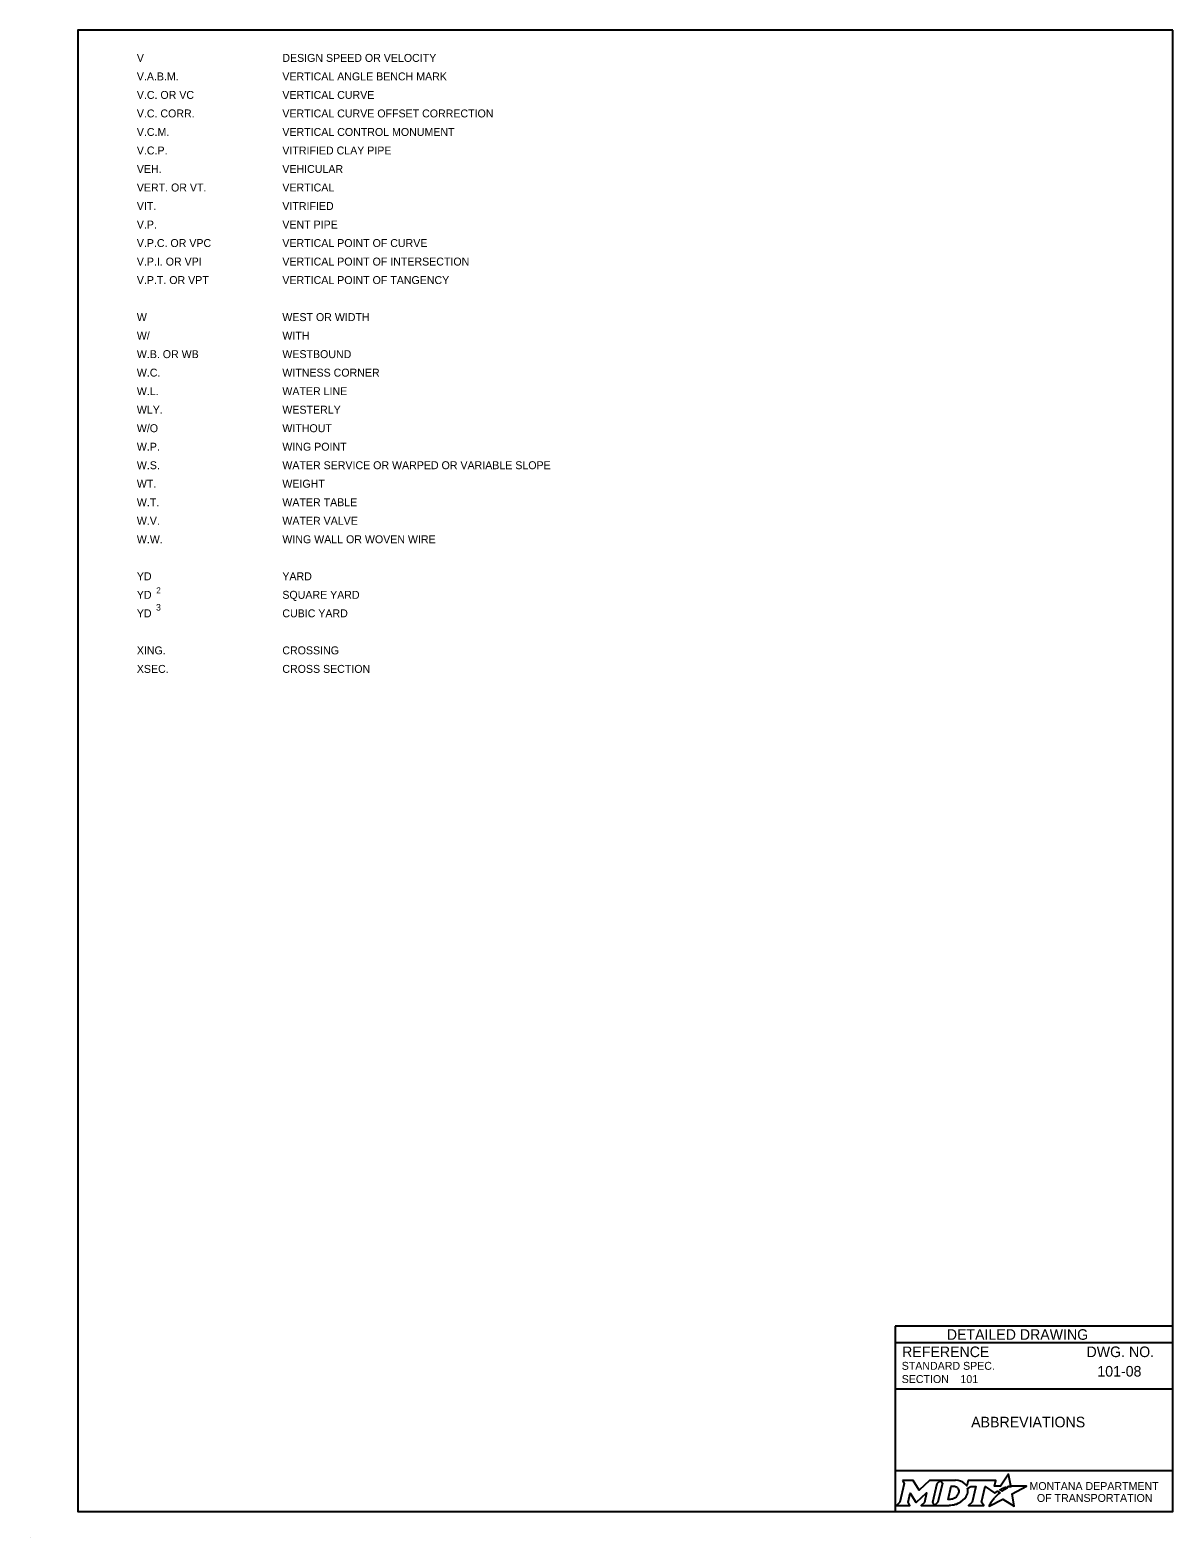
# Model space of a CAD drawing. Extents: x 49991.4 to 50021, y 49987.6 to 50011.4.
# Drawn here: x 49999.98 to 50008.61, y 49999.86 to 50011.26 of the extents above; entities that cross this region are included whole.
import ezdxf

# ---------------------------------------------------------------- set-up
doc = ezdxf.new("R2010")
doc.units = 0
for name, color, linetype in [('Default', 7, 'Continuous'), ('Level 1', 7, 'Continuous'), ('Level 2', 7, 'Continuous'), ('Level 5', 7, 'Continuous')]:
    doc.layers.add(name, color=color, linetype=linetype)

msp = doc.modelspace()

# ---------------------------------------------------------------- linework, layer by layer
at = {"layer": 'Level 1'}
msp.add_line((49999.977, 49999.862), (49999.977, 49999.862), dxfattribs=at)
msp.add_lwpolyline([(50008.615, 50011.263), (50000.336, 50011.263), (50000.336, 50000.062), (50008.615, 50000.062)], close=True, dxfattribs=at)
at = {"layer": 'Level 2'}
for p, q in [((50008.615, 50001.462), (50006.515, 50001.462)), ((50006.515, 50001.462), (50006.515, 50000.062)), ((50008.615, 50001.337), (50006.515, 50001.337)), ((50007.009, 50001.063), (50007.009, 50001.063)), ((50008.251, 50001.122), (50008.251, 50001.122)), ((50008.615, 50000.987), (50006.515, 50000.987)), ((50007.565, 50000.738), (50007.565, 50000.738)), ((50008.615, 50000.369), (50006.515, 50000.369))]:
    msp.add_line(p, q, dxfattribs=at)
for points in [[(50007.377, 50000.245), (50007.367, 50000.25), (50007.378, 50000.253), (50007.39, 50000.255), (50007.373, 50000.345), (50007.313, 50000.254), (50007.266, 50000.253), (50007.276, 50000.297), (50007.067, 50000.297), (50007.057, 50000.255), (50007.051, 50000.263)], [(50006.57, 50000.297), (50006.584, 50000.274), (50006.551, 50000.131), (50006.525, 50000.108), (50006.627, 50000.108), (50006.613, 50000.131), (50006.629, 50000.201), (50006.673, 50000.132), (50006.678, 50000.132), (50006.753, 50000.202), (50006.737, 50000.13), (50006.712, 50000.108), (50006.814, 50000.108), (50006.8, 50000.132), (50006.833, 50000.274)], [(50006.833, 50000.274), (50006.859, 50000.297), (50006.776, 50000.297), (50006.697, 50000.224), (50006.652, 50000.297), (50006.57, 50000.297)], [(50006.972, 50000.297), (50006.859, 50000.297), (50006.873, 50000.275), (50006.839, 50000.131), (50006.814, 50000.108), (50006.925, 50000.108)], [(50006.996, 50000.211), (50006.995, 50000.203), (50006.992, 50000.193), (50006.988, 50000.185), (50006.982, 50000.178), (50006.976, 50000.171), (50006.968, 50000.164), (50006.959, 50000.16), (50006.95, 50000.156), (50006.941, 50000.154), (50006.932, 50000.153), (50006.916, 50000.153), (50006.94, 50000.253), (50006.956, 50000.253), (50006.963, 50000.252), (50006.971, 50000.25), (50006.977, 50000.247), (50006.983, 50000.243), (50006.988, 50000.238), (50006.992, 50000.232), (50006.995, 50000.226), (50006.996, 50000.218), (50006.996, 50000.215), (50006.996, 50000.211)], [(50007.064, 50000.238), (50007.088, 50000.251), (50007.125, 50000.251), (50007.097, 50000.131), (50007.069, 50000.108), (50007.185, 50000.108), (50007.168, 50000.131), (50007.196, 50000.251), (50007.268, 50000.2), (50007.289, 50000.215), (50007.309, 50000.204)], [(50007.253, 50000.148), (50007.237, 50000.124), (50007.233, 50000.116), (50007.227, 50000.107), (50007.225, 50000.103), (50007.33, 50000.156), (50007.414, 50000.101), (50007.401, 50000.194), (50007.508, 50000.252), (50007.458, 50000.253), (50007.428, 50000.253), (50007.407, 50000.254), (50007.401, 50000.252), (50007.396, 50000.251), (50007.387, 50000.249), (50007.377, 50000.245)], [(50007.327, 50000.217), (50007.324, 50000.215), (50007.306, 50000.225), (50007.316, 50000.231), (50007.32, 50000.233), (50007.329, 50000.237), (50007.335, 50000.239), (50007.343, 50000.243), (50007.35, 50000.245), (50007.362, 50000.238), (50007.358, 50000.236), (50007.353, 50000.233), (50007.349, 50000.231), (50007.344, 50000.228), (50007.342, 50000.227), (50007.339, 50000.225), (50007.337, 50000.224), (50007.334, 50000.222), (50007.332, 50000.221), (50007.329, 50000.219), (50007.327, 50000.217)], [(50006.97, 50000.116), (50006.979, 50000.118), (50006.992, 50000.124), (50007.012, 50000.135)], [(50007.267, 50000.164), (50007.267, 50000.164)]]:
    msp.add_lwpolyline(points, dxfattribs=at)
for centre, radius, start, end in [((50006.995, 50000.219), 0.0709, 339.5329, 15.8582), ((50006.951, 50000.236), 0.118, 300.9103, 339.1383)]:
    msp.add_arc(centre, radius, start, end, dxfattribs=at)
for centre, major_axis, ratio, start_param, end_param in [((50006.97, 50000.25), (0.0834, -0.0037), 0.568097, 0.61298, 1.570796), ((50007.026, 50000.257), (0.0361, -0.0295), 0.469099, 1.225588, 1.570796), ((50006.925, 50000.257), (0, 0.148), 0.987302, 3.139398, 3.456847), ((50007.26, 50000.156), (-0.00694, -0.00806), 0.008222, 0, 3.137361), ((50007.276, 50000.174), (-0.0098, -0.0102), 0.016458, 3.141593, 6.279097), ((50007.297, 50000.194), (-0.0112, -0.0097), 0.021651, 3.157348, 6.283185)]:
    msp.add_ellipse(centre, major_axis=major_axis, ratio=ratio, start_param=start_param, end_param=end_param, dxfattribs=at)

# ---------------------------------------------------------------- texts
at = {"layer": 'Default'}
for s, height, p in [('2', 0.0456, (50000.93, 50007.004)), ('3', 0.0493, (50000.928, 50006.874))]:
    msp.add_text(s, height=height, dxfattribs=at).set_placement(p)
at = {"layer": 'Level 2'}
for s, height, p in [('V              ', 0.06, (50000.783, 50011.023)), ('DESIGN SPEED OR VELOCITY                ', 0.06, (50001.883, 50011.023)), ('V.A.B.M.       ', 0.06, (50000.783, 50010.883)), ('VERTICAL ANGLE BENCH MARK               ', 0.06, (50001.883, 50010.883)), ('V.C. OR VC     ', 0.06, (50000.783, 50010.743)), ('VERTICAL CURVE                          ', 0.06, (50001.883, 50010.743)), ('V.C. CORR.     ', 0.06, (50000.783, 50010.603)), ('VERTICAL CURVE OFFSET CORRECTION        ', 0.06, (50001.883, 50010.603)), ('V.C.M.         ', 0.06, (50000.783, 50010.463)), ('VERTICAL CONTROL MONUMENT               ', 0.06, (50001.883, 50010.463)), ('V.C.P.         ', 0.06, (50000.783, 50010.323)), ('VITRIFIED CLAY PIPE                     ', 0.06, (50001.883, 50010.323)), ('VEH.           ', 0.06, (50000.783, 50010.183)), ('VEHICULAR                               ', 0.06, (50001.883, 50010.183)), ('VERT. OR VT.   ', 0.06, (50000.783, 50010.043)), ('VERTICAL                                ', 0.06, (50001.883, 50010.043)), ('VIT.           ', 0.06, (50000.783, 50009.903)), ('VITRIFIED                               ', 0.06, (50001.883, 50009.903)), ('V.P.           ', 0.06, (50000.783, 50009.763)), ('VENT PIPE                               ', 0.06, (50001.883, 50009.763)), ('V.P.C. OR VPC  ', 0.06, (50000.783, 50009.623)), ('VERTICAL POINT OF CURVE                 ', 0.06, (50001.883, 50009.623)), ('V.P.I. OR VPI  ', 0.06, (50000.783, 50009.483)), ('VERTICAL POINT OF INTERSECTION          ', 0.06, (50001.883, 50009.483)), ('V.P.T. OR VPT  ', 0.06, (50000.783, 50009.343)), ('VERTICAL POINT OF TANGENCY              ', 0.06, (50001.883, 50009.343)), ('W              ', 0.06, (50000.783, 50009.063)), ('WEST OR WIDTH                                    ', 0.06, (50001.883, 50009.063)), ('W/             ', 0.06, (50000.783, 50008.923)), ('WITH                                    ', 0.06, (50001.883, 50008.923)), ('W.B. OR WB     ', 0.06, (50000.783, 50008.783)), ('WESTBOUND                               ', 0.06, (50001.883, 50008.783)), ('W.C.           ', 0.06, (50000.783, 50008.643)), ('WITNESS CORNER                          ', 0.06, (50001.883, 50008.643)), ('W.L.           ', 0.06, (50000.783, 50008.503)), ('WATER LINE                              ', 0.06, (50001.883, 50008.503)), ('WLY.           ', 0.06, (50000.783, 50008.363)), ('WESTERLY                                ', 0.06, (50001.883, 50008.363)), ('W/O            ', 0.06, (50000.783, 50008.223)), ('WITHOUT                                 ', 0.06, (50001.883, 50008.223)), ('W.P.           ', 0.06, (50000.783, 50008.083)), ('WING POINT                              ', 0.06, (50001.883, 50008.083)), ('W.S.           ', 0.06, (50000.783, 50007.943)), ('WATER SERVICE OR WARPED OR VARIABLE SLOPE', 0.06, (50001.883, 50007.943)), ('WT.            ', 0.06, (50000.783, 50007.803)), ('WEIGHT                                  ', 0.06, (50001.883, 50007.803)), ('W.T.           ', 0.06, (50000.783, 50007.663)), ('WATER TABLE                             ', 0.06, (50001.883, 50007.663)), ('W.V.           ', 0.06, (50000.783, 50007.523)), ('WATER VALVE                             ', 0.06, (50001.883, 50007.523)), ('W.W.           ', 0.06, (50000.783, 50007.383)), ('WING WALL OR WOVEN WIRE                 ', 0.06, (50001.883, 50007.383)), ('YD             ', 0.06, (50000.783, 50007.103)), ('YARD                                    ', 0.06, (50001.883, 50007.103)), ('YD             ', 0.06, (50000.783, 50006.963)), ('SQUARE YARD                             ', 0.06, (50001.883, 50006.963)), ('YD             ', 0.06, (50000.783, 50006.823)), ('CUBIC YARD                              ', 0.06, (50001.883, 50006.823)), ('XING.          ', 0.06, (50000.783, 50006.543)), ('CROSSING                                ', 0.06, (50001.883, 50006.543)), ('XSEC.          ', 0.06, (50000.783, 50006.403)), ('CROSS SECTION                           ', 0.06, (50001.883, 50006.403)), ('REFERENCE', 0.08, (50006.568, 50001.229)), ('DWG. NO.', 0.08, (50007.962, 50001.229)), ('STANDARD SPEC.', 0.06, (50006.565, 50001.133)), ('101-08', 0.08, (50008.044, 50001.082)), ('SECTION', 0.06, (50006.565, 50001.033)), ('101', 0.06, (50007.009, 50001.033)), ('ABBREVIATIONS', 0.08, (50007.09, 50000.698)), ('MONTANA DEPARTMENT', 0.06, (50007.531, 50000.224)), ('OF TRANSPORTATION', 0.06, (50007.587, 50000.134))]:
    msp.add_text(s, height=height, dxfattribs=at).set_placement(p)
at = {"layer": 'Level 5'}
msp.add_text('DETAILED DRAWING', height=0.0799, dxfattribs=at).set_placement((50006.906, 50001.36))

doc.saveas('drawing.dxf')
